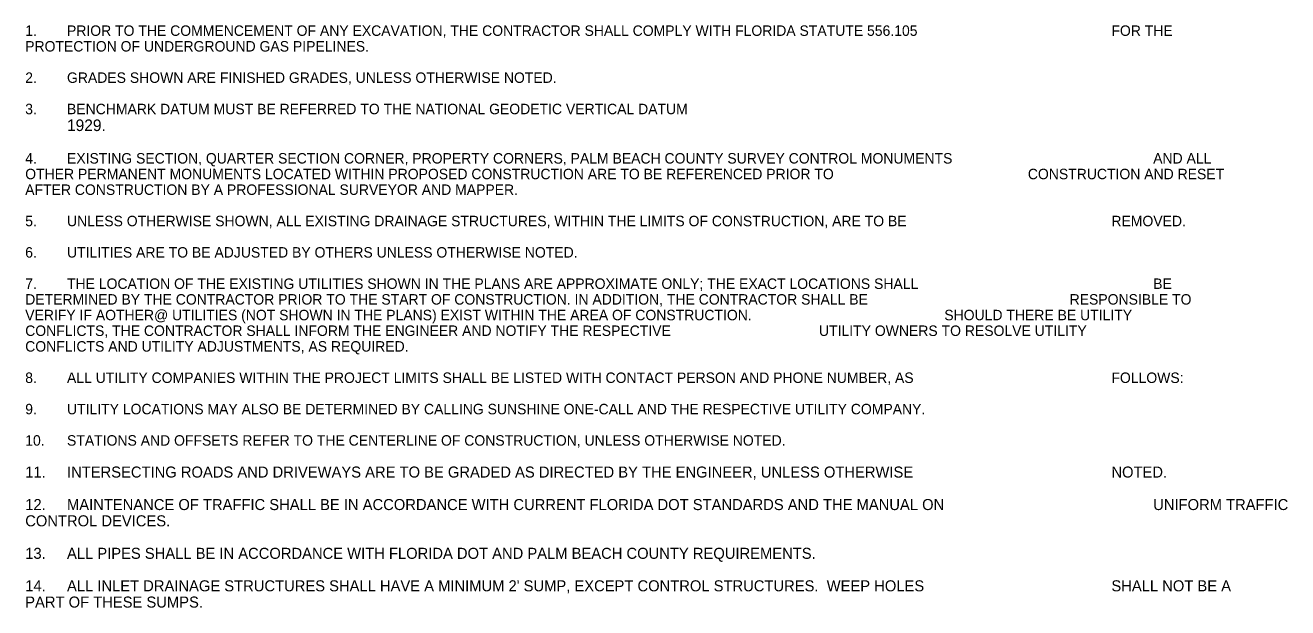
# Model space of a CAD drawing. Extents: x 783907 to 784590, y 832093 to 832609.
# Drawn here: x 784002.1 to 784086.7, y 832393.5 to 832432.5 of the extents above; entities that cross this region are included whole.
import ezdxf

# ---------------------------------------------------------------- set-up
doc = ezdxf.new("R2010")
doc.units = 0
doc.layers.add('TextLabel', color=7, linetype='Continuous')

msp = doc.modelspace()

# ---------------------------------------------------------------- texts
at = {"layer": 'TextLabel'}
for s, height, p in [('1.', 0.7, (784002.096, 832431.818)), ('PRIOR TO THE COMMENCEMENT OF ANY EXCAVATION, THE CONTRACTOR SHALL COMPLY WITH FLORIDA STATUTE 556.105 ', 0.7, (784004.896, 832431.818)), ('FOR THE ', 0.7, (784074.896, 832431.818)), ('PROTECTION OF UNDERGROUND GAS PIPELINES.', 0.7, (784002.096, 832430.768)), ('2.', 0.7, (784002.096, 832428.668)), ('GRADES SHOWN ARE FINISHED GRADES, UNLESS OTHERWISE NOTED.', 0.7, (784004.896, 832428.668)), ('3.', 0.7, (784002.096, 832426.568)), ('BENCHMARK DATUM MUST BE REFERRED TO THE NATIONAL GEODETIC VERTICAL DATUM', 0.7, (784004.896, 832426.568)), ('1929.', 0.7778, (784004.896, 832425.44)), ('4.', 0.7, (784002.096, 832423.263)), ('EXISTING SECTION, QUARTER SECTION CORNER, PROPERTY CORNERS, PALM BEACH COUNTY SURVEY CONTROL MONUMENTS ', 0.7, (784004.896, 832423.263)), ('AND ALL ', 0.7, (784077.696, 832423.263)), ('OTHER PERMANENT MONUMENTS LOCATED WITHIN PROPOSED CONSTRUCTION ARE TO BE REFERENCED PRIOR TO ', 0.7, (784002.096, 832422.213)), ('CONSTRUCTION AND RESET ', 0.7, (784069.296, 832422.213)), ('AFTER CONSTRUCTION BY A PROFESSIONAL SURVEYOR AND MAPPER.', 0.7, (784002.096, 832421.163)), ('5.', 0.7, (784002.096, 832419.063)), ('UNLESS OTHERWISE SHOWN, ALL EXISTING DRAINAGE STRUCTURES, WITHIN THE LIMITS OF CONSTRUCTION, ARE TO BE ', 0.7, (784004.896, 832419.063)), ('REMOVED.', 0.7, (784074.896, 832419.063)), ('6.', 0.7, (784002.096, 832416.963)), ('UTILITIES ARE TO BE ADJUSTED BY OTHERS UNLESS OTHERWISE NOTED.', 0.7, (784004.896, 832416.963)), ('7.', 0.7, (784002.096, 832414.863)), ('THE LOCATION OF THE EXISTING UTILITIES SHOWN IN THE PLANS ARE APPROXIMATE ONLY; THE EXACT LOCATIONS SHALL ', 0.7, (784004.896, 832414.863)), ('BE ', 0.7, (784077.696, 832414.863)), ('DETERMINED BY THE CONTRACTOR PRIOR TO THE START OF CONSTRUCTION. IN ADDITION, THE CONTRACTOR SHALL BE ', 0.7, (784002.096, 832413.813)), ('RESPONSIBLE TO ', 0.7, (784072.096, 832413.813)), ('VERIFY IF AOTHER@ UTILITIES (NOT SHOWN IN THE PLANS) EXIST WITHIN THE AREA OF CONSTRUCTION. ', 0.7, (784002.096, 832412.763)), ('SHOULD THERE BE UTILITY ', 0.7, (784063.696, 832412.763)), ('CONFLICTS, THE CONTRACTOR SHALL INFORM THE ENGINEER AND NOTIFY THE RESPECTIVE ', 0.7, (784002.096, 832411.713)), ('UTILITY OWNERS TO RESOLVE UTILITY ', 0.7, (784055.296, 832411.713)), ('CONFLICTS AND UTILITY ADJUSTMENTS, AS REQUIRED.', 0.7, (784002.096, 832410.663)), ('8.', 0.7, (784002.096, 832408.563)), ('ALL UTILITY COMPANIES WITHIN THE PROJECT LIMITS SHALL BE LISTED WITH CONTACT PERSON AND PHONE NUMBER, AS ', 0.7, (784004.896, 832408.563)), ('FOLLOWS:', 0.7, (784074.896, 832408.563)), ('9.', 0.7, (784002.096, 832406.463)), ('UTILITY LOCATIONS MAY ALSO BE DETERMINED BY CALLING SUNSHINE ONE-CALL AND THE RESPECTIVE UTILITY COMPANY.', 0.7, (784004.896, 832406.463)), ('10.', 0.7, (784002.096, 832404.363)), ('STATIONS AND OFFSETS REFER TO THE CENTERLINE OF CONSTRUCTION, UNLESS OTHERWISE NOTED.', 0.7, (784004.896, 832404.363)), ('11.', 0.7389, (784002.096, 832402.224)), ('INTERSECTING ROADS AND DRIVEWAYS ARE TO BE GRADED AS DIRECTED BY THE ENGINEER, UNLESS OTHERWISE ', 0.73889, (784004.896, 832402.224)), ('NOTED.', 0.7389, (784074.896, 832402.224)), ('12.', 0.7389, (784002.096, 832400.046)), ('MAINTENANCE OF TRAFFIC SHALL BE IN ACCORDANCE WITH CURRENT FLORIDA DOT STANDARDS AND THE MANUAL ON ', 0.73889, (784004.896, 832400.046)), ('UNIFORM TRAFFIC ', 0.73889, (784077.696, 832400.046)), ('CONTROL DEVICES.', 0.73889, (784002.096, 832398.957)), ('13.', 0.7389, (784002.096, 832396.779)), ('ALL PIPES SHALL BE IN ACCORDANCE WITH FLORIDA DOT AND PALM BEACH COUNTY REQUIREMENTS.', 0.73889, (784004.896, 832396.779)), ('14.', 0.7389, (784002.096, 832394.602)), ("ALL INLET DRAINAGE STRUCTURES SHALL HAVE A MINIMUM 2' SUMP, EXCEPT CONTROL STRUCTURES.  WEEP HOLES ", 0.73889, (784004.896, 832394.602)), ('SHALL NOT BE A ', 0.73889, (784074.896, 832394.602)), ('PART OF THESE SUMPS.', 0.73889, (784002.096, 832393.513))]:
    msp.add_text(s, height=height, dxfattribs=at).set_placement(p)

doc.saveas('drawing.dxf')
